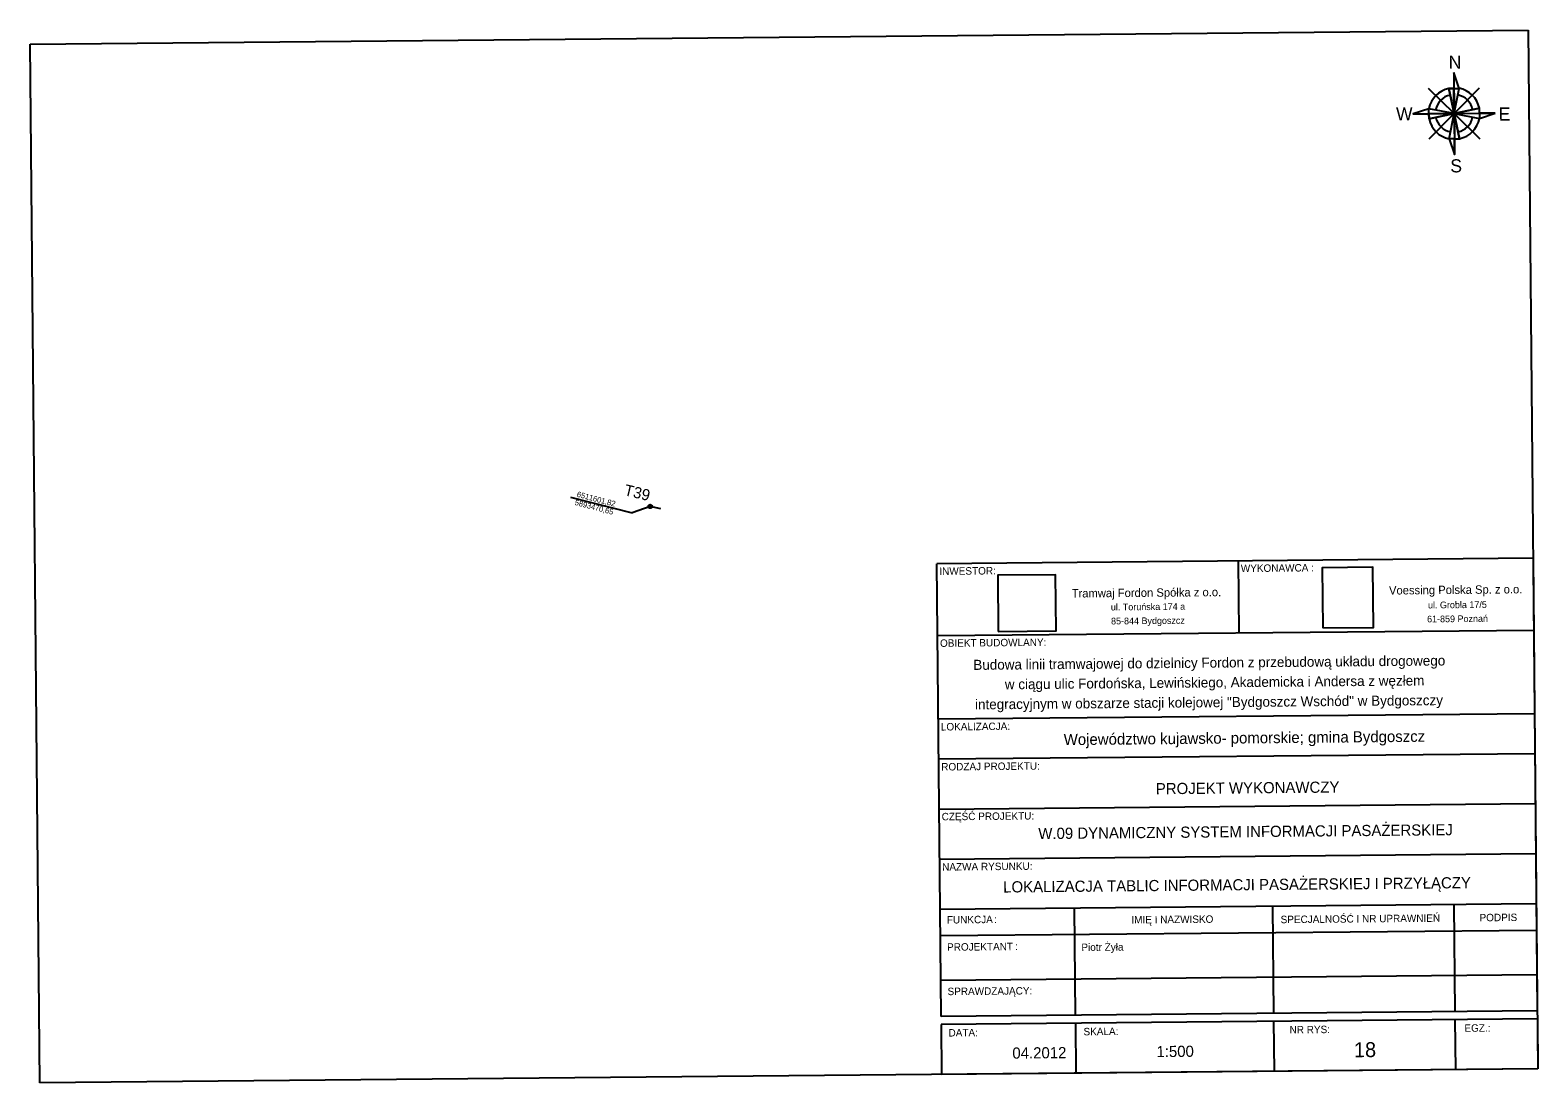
# Model space of a CAD drawing. Extents: x 6505045 to 6511721, y 5887996 to 5893535.
# Drawn here: x 6511518.6 to 6511720.9, y 5893393.3 to 5893534.6 of the extents above; entities that cross this region are included whole.
import ezdxf

# ---------------------------------------------------------------- set-up
doc = ezdxf.new("R2010")
doc.units = 0
for name, color, linetype in [('__legenda', 7, 'Continuous'), ('Default', 7, 'Continuous'), ('P_2 tablice LCD', 7, 'Continuous'), ('P_lokalizacja slupka', 7, 'Continuous'), ('P_opisy', 7, 'Continuous'), ('P_tabela', 7, 'Continuous'), ('P_wsporzedne', 7, 'Continuous'), ('P_znak północy', 7, 'Continuous'), ('SA_Linie-020', 7, 'Continuous'), ('SA_Stempel_Text-020', 7, 'Continuous'), ('SA_Stempel_Text-030', 7, 'Continuous'), ('SA_Stempel_Text-035', 7, 'Continuous'), ('SA_Unterschrift_Text', 7, 'Continuous')]:
    doc.layers.add(name, color=color, linetype=linetype)

msp = doc.modelspace()

# ---------------------------------------------------------------- linework, layer by layer
at = {"layer": '__legenda'}
msp.add_lwpolyline([(6511692.05, 5893454.34), (6511698.85, 5893454.41), (6511698.77, 5893462.47), (6511691.97, 5893462.41)], close=True, dxfattribs=at)
at = {"layer": 'Default'}
msp.add_lwpolyline([(6511648.52, 5893453.87), (6511656.26, 5893453.94), (6511656.19, 5893461.48), (6511648.45, 5893461.41)], close=True, dxfattribs=at)
at = {"layer": 'P_2 tablice LCD'}
msp.add_line((6511603.23, 5893470.3), (6511601.82, 5893470.65), dxfattribs=at)
at = {"layer": 'P_lokalizacja slupka'}
msp.add_circle((6511601.82, 5893470.65), 0.25, dxfattribs=at)
at = {"layer": 'P_tabela'}
for p, q in [((6511518.62, 5893532.71), (6511719.6, 5893534.58)), ((6511719.6, 5893534.58), (6511720.91, 5893395.14)), ((6511519.92, 5893393.26), (6511518.62, 5893532.71)), ((6511720.91, 5893395.14), (6511519.92, 5893393.26))]:
    msp.add_line(p, q, dxfattribs=at)
at = {"layer": 'P_wsporzedne'}
for p in [(6511591.12, 5893471.9), (6511601.82, 5893470.65)]:
    msp.add_line(p, (6511599.38, 5893469.8), dxfattribs=at)
at = {"layer": 'P_znak północy'}
for p, q in [((6511709.63, 5893528.91), (6511709.73, 5893517.87)), ((6511709.67, 5893523.39), (6511706.24, 5893526.77)), ((6511708.96, 5893526.76), (6511709.65, 5893526.77)), ((6511709.68, 5893523.39), (6511708.96, 5893526.76)), ((6511709.65, 5893526.76), (6511710.34, 5893526.77)), ((6511709.68, 5893523.4), (6511713.07, 5893526.83)), ((6511709.68, 5893523.39), (6511710.34, 5893526.77)), ((6511704.16, 5893523.33), (6511715.2, 5893523.44)), ((6511709.68, 5893523.39), (6511706.3, 5893524.04)), ((6511709.68, 5893523.4), (6511706.3, 5893519.94)), ((6511706.3, 5893523.35), (6511709.67, 5893523.39)), ((6511706.31, 5893522.66), (6511709.68, 5893523.39)), ((6511709.67, 5893523.39), (6511706.31, 5893522.66)), ((6511709.02, 5893520), (6511709.68, 5893523.39)), ((6511709.68, 5893523.39), (6511713.06, 5893524.11)), ((6511709.68, 5893523.4), (6511713.13, 5893520)), ((6511709.68, 5893523.39), (6511713.07, 5893522.73)), ((6511709.68, 5893523.39), (6511710.41, 5893520.01)), ((6511706.31, 5893522.66), (6511706.3, 5893523.35))]:
    msp.add_line(p, q, dxfattribs=at)
for points in [[(6511709.63, 5893528.91), (6511709.65, 5893526.77), (6511709.65, 5893526.76), (6511710.34, 5893526.77), (6511709.63, 5893528.91)], [(6511709.68, 5893523.4), (6511709.65, 5893526.77), (6511708.96, 5893526.76), (6511709.68, 5893523.39), (6511709.68, 5893523.4)], [(6511706.3, 5893523.35), (6511706.3, 5893524.04), (6511704.16, 5893523.33), (6511706.3, 5893523.35)], [(6511709.67, 5893523.39), (6511706.3, 5893523.35), (6511706.31, 5893522.66), (6511709.67, 5893523.39)], [(6511709.68, 5893523.39), (6511709.68, 5893523.39), (6511709.69, 5893523.39), (6511713.06, 5893523.42), (6511713.06, 5893524.11), (6511709.68, 5893523.39)], [(6511709.71, 5893520.01), (6511710.41, 5893520.01), (6511709.68, 5893523.38), (6511709.71, 5893520.01)], [(6511715.2, 5893523.44), (6511713.06, 5893523.42), (6511713.07, 5893522.73), (6511715.2, 5893523.44)], [(6511709.71, 5893520.01), (6511709.02, 5893520), (6511709.73, 5893517.87), (6511709.71, 5893520.01)]]:
    msp.add_lwpolyline(points, dxfattribs=at)
for centre, radius, start, end in [((6511709.68, 5893523.39), 3.45, 102.0474, 168.9738), ((6511709.68, 5893523.4), 2.53, 102.1671, 169.2958), ((6511709.68, 5893523.4), 2.53, 11.7816, 78.9353), ((6511709.69, 5893523.39), 3.45, 12.0554, 79.0163), ((6511709.68, 5893523.38), 3.45, 192.0538, 259.0158), ((6511709.68, 5893523.4), 2.53, 192.3917, 259.0318), ((6511709.68, 5893523.4), 2.53, 282.0081, 348.6723), ((6511709.69, 5893523.38), 3.45, 282.0538, 349.0163)]:
    msp.add_arc(centre, radius, start, end, dxfattribs=at)
at = {"layer": 'SA_Linie-020'}
for p, q in [((6511720.27, 5893463.71), (6511640.27, 5893462.96)), ((6511640.7, 5893416.54), (6511640.27, 5893462.96)), ((6511680.72, 5893463.34), (6511680.81, 5893453.68)), ((6511720.27, 5893463.71), (6511720.83, 5893402.92)), ((6511640.36, 5893453.3), (6511720.36, 5893454.05)), ((6511720.46, 5893442.82), (6511640.46, 5893442.08)), ((6511720.51, 5893437.45), (6511640.51, 5893436.7)), ((6511720.57, 5893430.73), (6511640.58, 5893429.98)), ((6511720.57, 5893430.73), (6511640.58, 5893429.98)), ((6511720.64, 5893424.01), (6511640.64, 5893423.26)), ((6511720.7, 5893417.29), (6511640.7, 5893416.54)), ((6511640.84, 5893402.17), (6511640.7, 5893416.54)), ((6511658.86, 5893402.34), (6511658.72, 5893416.71)), ((6511685.3, 5893416.96), (6511685.43, 5893402.59)), ((6511709.63, 5893417.19), (6511709.77, 5893402.81)), ((6511720.73, 5893413.73), (6511640.74, 5893412.98)), ((6511720.79, 5893407.77), (6511640.79, 5893407.02)), ((6511720.83, 5893402.92), (6511640.84, 5893402.17)), ((6511720.84, 5893401.86), (6511640.85, 5893401.11)), ((6511640.85, 5893401.11), (6511640.91, 5893394.39)), ((6511658.87, 5893401.28), (6511658.93, 5893394.56)), ((6511685.44, 5893401.53), (6511685.51, 5893394.81)), ((6511709.78, 5893401.75), (6511709.84, 5893395.03)), ((6511720.84, 5893401.86), (6511720.91, 5893395.14)), ((6511720.91, 5893395.14), (6511640.91, 5893394.39))]:
    msp.add_line(p, q, dxfattribs=at)

# ---------------------------------------------------------------- texts
at = {"layer": 'P_opisy'}
msp.add_text('T39', height=1.502, rotation=346.5719, dxfattribs=at).set_placement((6511598.22, 5893472.17))
at = {"layer": 'P_wsporzedne'}
for s, p in [('5893470,65', (6511591.63, 5893470.86)), ('6511601,82', (6511591.91, 5893471.95))]:
    msp.add_text(s, height=0.751, rotation=345.3342, dxfattribs=at).set_placement(p)
at = {"layer": 'P_znak północy'}
for s, p in [('N', (6511708.95, 5893529.39)), ('W', (6511701.89, 5893522.46)), ('E', (6511715.66, 5893522.44)), ('S', (6511709.17, 5893515.48))]:
    msp.add_text(s, height=1.76, rotation=0.535, dxfattribs=at).set_placement(p)
at = {"layer": 'SA_Stempel_Text-020'}
for s, p in [('WYKONAWCA :', (6511681.06, 5893461.83)), ('INWESTOR:', (6511640.61, 5893461.45)), ('OBIEKT BUDOWLANY:', (6511640.7, 5893451.79)), ('LOKALIZACJA:', (6511640.81, 5893440.56)), ('RODZAJ PROJEKTU:', (6511640.86, 5893435.19)), ('CZĘŚĆ PROJEKTU:', (6511640.92, 5893428.5)), ('NAZWA RYSUNKU:', (6511640.99, 5893421.75)), ('FUNKCJA', (6511641.62, 5893414.65)), (':', (6511647.95, 5893414.71)), ('IMIĘ I NAZWISKO', (6511666.38, 5893414.65)), ('SPECJALNOŚĆ I NR UPRAWNIEŃ', (6511686.4, 5893414.69)), ('PODPIS', (6511713.09, 5893414.94)), ('PROJEKTANT', (6511641.65, 5893410.99)), (':', (6511650.78, 5893411.08)), ('SPRAWDZAJĄCY:', (6511641.71, 5893405.03)), ('DATA:', (6511641.84, 5893399.48)), ('SKALA:', (6511659.95, 5893399.64)), ('NR RYS:', (6511687.6, 5893399.89)), ('EGZ.:', (6511711.06, 5893400.11))]:
    msp.add_text(s, height=1, rotation=0.535, dxfattribs=at).set_placement(p)
at = {"layer": 'SA_Stempel_Text-030'}
for s, height, p in [('04.2012', 1.5, (6511650.41, 5893396.51)), ('1:500', 1.5, (6511669.74, 5893396.71)), ('18', 2, (6511696.24, 5893396.7))]:
    msp.add_text(s, height=height, rotation=0.535, dxfattribs=at).set_placement(p)
at = {"layer": 'SA_Stempel_Text-035'}
for s, height, p in [('Budowa linii tramwajowej do dzielnicy Fordon z przebudową układu drogowego', 1.35, (6511645.17, 5893448.7)), ('w ciągu ulic Fordońska, Lewińskiego, Akademicka i Andersa z węzłem', 1.35, (6511649.4, 5893446.09)), ('integracyjnym w obszarze stacji kolejowej "Bydgoszcz Wschód" w Bydgoszczy', 1.35, (6511645.4, 5893443.39)), ('Województwo kujawsko- pomorskie; gmina Bydgoszcz', 1.5, (6511657.3, 5893438.6)), ('PROJEKT WYKONAWCZY', 1.5, (6511669.66, 5893432)), ('W.09 DYNAMICZNY SYSTEM INFORMACJI PASAŻERSKIEJ', 1.5, (6511653.89, 5893425.98)), ('LOKALIZACJA TABLIC INFORMACJI PASAŻERSKIEJ I PRZYŁĄCZY', 1.5, (6511649.18, 5893418.81))]:
    msp.add_text(s, height=height, rotation=0.535, dxfattribs=at).set_placement(p)
at = {"layer": 'SA_Unterschrift_Text'}
for s, height, p in [('Tramwaj Fordon Spółka z o.o.', 1.125, (6511658.36, 5893458.41)), ('Voessing Polska Sp. z o.o.', 1.125, (6511700.94, 5893458.81)), ('ul. Toruńska 174 a', 0.9, (6511663.62, 5893456.68)), ('ul. Grobla 17/5', 0.9, (6511706.17, 5893456.95)), ('85-844 Bydgoszcz', 0.9, (6511663.65, 5893454.8)), ('61-859 Poznań', 0.9, (6511706.05, 5893455.07)), ('Piotr Żyła', 1, (6511659.67, 5893410.96))]:
    msp.add_text(s, height=height, rotation=0.535, dxfattribs=at).set_placement(p)

doc.saveas('drawing.dxf')
